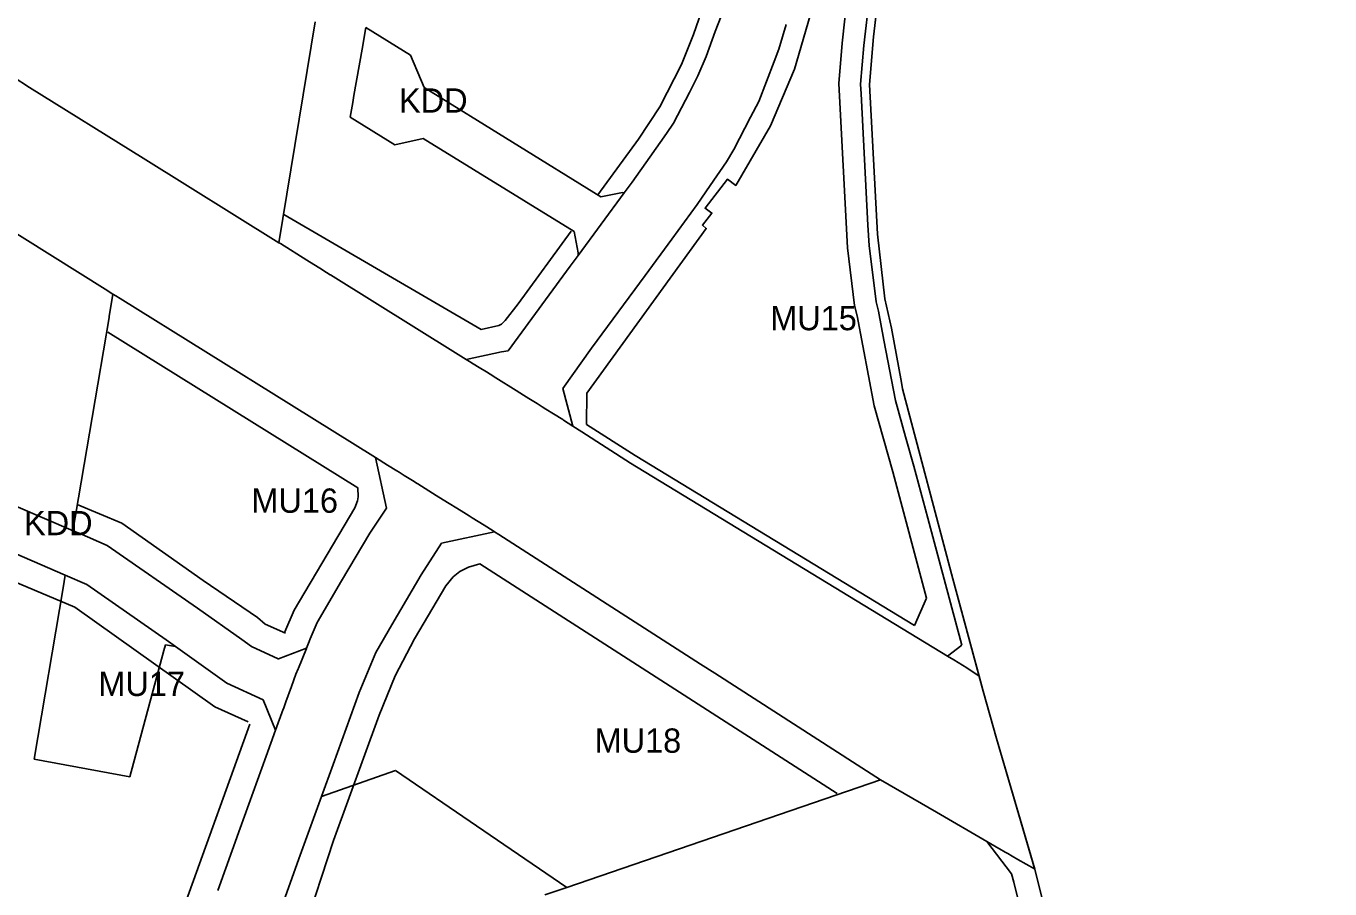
# Model space of a CAD drawing. Extents: x 7428080 to 7432143, y 5545880 to 5549217.
# Drawn here: x 7430887.1 to 7431185, y 5547031.3 to 5547228.4 of the extents above; entities that cross this region are included whole.
import ezdxf

# ---------------------------------------------------------------- set-up
doc = ezdxf.new("R2010")
doc.units = 0
for name, color, linetype in [('CZ_L_granica obszaru objętego planem', 7, 'Continuous'), ('CZ_L_linie rozgraniczające tereny o różnym przeznaczeniu oraz różnych warunkach ich zabudowy i zagospodarowania', 7, 'Continuous'), ('CZ_L_maksymalne nieprzekraczalne linie zabudowy', 7, 'Continuous'), ('CZ_L_opisy_linie rozgraniczające tereny o różnym przeznaczeniu oraz różnych warunkach ich zabudowy i zagospodarowania', 7, 'Continuous')]:
    doc.layers.add(name, color=color, linetype=linetype)

msp = doc.modelspace()

# ---------------------------------------------------------------- linework, layer by layer
at = {"layer": 'CZ_L_granica obszaru objętego planem'}
for p, q in [((7431083.35, 5547248.03), (7431080.69, 5547225.95)), ((7431080.69, 5547225.95), (7431079.79, 5547215.06)), ((7431079.79, 5547215.06), (7431081.67, 5547180.91)), ((7431081.67, 5547180.91), (7431083.32, 5547166.12)), ((7431083.32, 5547166.12), (7431084.84, 5547159.41)), ((7431084.84, 5547159.41), (7431087.12, 5547146.98)), ((7431087.12, 5547146.98), (7431087.38, 5547145.53)), ((7431087.38, 5547145.53), (7431098.88, 5547102.12)), ((7431098.88, 5547102.12), (7431105.77, 5547076.46)), ((7431105.77, 5547076.46), (7431108.82, 5547065.62)), ((7431108.82, 5547065.62), (7431117.61, 5547035.75)), ((7431117.61, 5547035.75), (7431121.32, 5547020.82))]:
    msp.add_line(p, q, dxfattribs=at)
at = {"layer": 'CZ_L_linie rozgraniczające tereny o różnym przeznaczeniu oraz różnych warunkach ich zabudowy i zagospodarowania'}
for p, q in [((7431080.54, 5547241.86), (7431078.52, 5547223.98)), ((7430944.87, 5547178.9), (7430953.17, 5547229.4)), ((7431045.9, 5547230.71), (7431044.58, 5547227.18)), ((7430964.71, 5547228.06), (7430963.85, 5547223.13)), ((7430974.92, 5547221.75), (7430964.71, 5547228.06)), ((7431044.58, 5547227.18), (7431042.46, 5547221.47)), ((7431059.1, 5547223.16), (7431060.78, 5547228.77)), ((7430963.85, 5547223.13), (7430961.99, 5547212.53)), ((7430963.85, 5547223.13), (7430963.85, 5547223.13)), ((7431058.01, 5547220.33), (7431059.1, 5547223.16)), ((7431078.52, 5547223.98), (7431077.77, 5547215.15)), ((7430887.88, 5547214.39), (7430874.73, 5547222.87)), ((7430978.01, 5547214.39), (7430974.92, 5547221.75)), ((7431042.46, 5547221.47), (7431040.61, 5547217.03)), ((7431054.49, 5547211.2), (7431058.01, 5547220.33)), ((7430913.85, 5547198.22), (7430887.88, 5547214.39)), ((7431018.42, 5547189.42), (7430978.01, 5547214.39)), ((7431040.61, 5547217.03), (7431038.71, 5547213.27)), ((7431077.77, 5547215.15), (7431077.87, 5547212.96)), ((7430961.99, 5547212.53), (7430961.71, 5547210.92)), ((7431038.71, 5547213.27), (7431035.02, 5547206.25)), ((7431052.64, 5547207.64), (7431054.49, 5547211.2)), ((7431077.87, 5547212.96), (7431079.41, 5547182.9)), ((7430961.71, 5547210.92), (7430961.13, 5547207.61)), ((7430961.13, 5547207.61), (7430971.33, 5547201.3)), ((7431035.02, 5547206.25), (7431033.39, 5547203.87)), ((7431048.79, 5547200.23), (7431052.64, 5547207.64)), ((7430971.33, 5547201.3), (7430977.83, 5547202.74)), ((7430977.83, 5547202.74), (7431012.3, 5547181.45)), ((7431033.39, 5547203.87), (7431029.6, 5547198.43)), ((7431047.14, 5547197.41), (7431048.79, 5547200.23)), ((7430944.87, 5547178.9), (7430913.85, 5547198.22)), ((7431029.6, 5547198.43), (7431025.55, 5547192.79)), ((7431043.42, 5547191.99), (7431047.14, 5547197.41)), ((7431023.75, 5547190.33), (7431013.26, 5547176.03)), ((7431023.34, 5547190.37), (7431018.42, 5547189.42)), ((7431023.75, 5547190.33), (7431023.34, 5547190.37)), ((7431025.55, 5547192.79), (7431023.75, 5547190.33)), ((7431040.41, 5547187.68), (7431043.42, 5547191.99)), ((7430871.92, 5547188.98), (7430905.11, 5547168.32)), ((7431034.61, 5547179.76), (7431040.41, 5547187.68)), ((7431012.3, 5547181.45), (7431013.23, 5547176.59)), ((7431079.41, 5547182.9), (7431079.74, 5547178.29)), ((7430945.18, 5547178.71), (7430944.87, 5547178.9)), ((7430951.25, 5547174.93), (7430945.18, 5547178.71)), ((7431028.52, 5547171.43), (7431034.61, 5547179.76)), ((7431013.26, 5547176.03), (7431011.44, 5547173.55)), ((7431013.23, 5547176.59), (7431013.26, 5547176.03)), ((7431079.74, 5547178.29), (7431081.32, 5547165.45)), ((7430954.81, 5547172.71), (7430951.25, 5547174.93)), ((7430954.87, 5547172.67), (7430954.81, 5547172.71)), ((7430956.6, 5547171.6), (7430954.87, 5547172.67)), ((7431011.44, 5547173.55), (7431005.77, 5547165.86)), ((7430956.62, 5547171.58), (7430956.6, 5547171.6)), ((7430956.63, 5547171.58), (7430956.62, 5547171.58)), ((7430985.8, 5547153.41), (7430956.63, 5547171.58)), ((7430956.63, 5547171.58), (7430956.63, 5547171.58)), ((7431016.28, 5547154.85), (7431028.52, 5547171.43)), ((7430905.11, 5547168.32), (7430906.9, 5547167.2)), ((7430906.9, 5547167.2), (7430906.09, 5547162.04)), ((7430906.9, 5547167.2), (7430907.6, 5547166.77)), ((7430907.6, 5547166.77), (7430908.58, 5547166.16)), ((7430908.58, 5547166.16), (7430947.72, 5547141.79)), ((7431005.77, 5547165.86), (7430997.25, 5547154.25)), ((7431081.32, 5547165.45), (7431081.9, 5547163.27)), ((7430906.05, 5547161.84), (7430903.45, 5547146.57)), ((7430906.09, 5547162.04), (7430906.05, 5547161.84)), ((7431081.9, 5547163.27), (7431083.06, 5547156.68)), ((7431009.73, 5547145.58), (7431016.28, 5547154.85)), ((7431083.06, 5547156.68), (7431085.77, 5547142.86)), ((7430987.64, 5547152.27), (7430985.8, 5547153.41)), ((7430995.68, 5547153.96), (7430987.64, 5547152.27)), ((7430987.64, 5547152.27), (7430988.41, 5547151.79)), ((7430988.41, 5547151.79), (7430988.6, 5547151.67)), ((7430988.6, 5547151.67), (7430990.26, 5547150.64)), ((7430997.25, 5547154.25), (7430995.68, 5547153.96)), ((7430990.26, 5547150.64), (7430992.64, 5547149.16)), ((7430992.64, 5547149.16), (7430992.78, 5547149.09)), ((7430992.78, 5547149.09), (7430993.12, 5547148.88)), ((7430993.12, 5547148.88), (7430994.41, 5547148.07)), ((7430903.45, 5547146.57), (7430899.03, 5547120.61)), ((7430994.41, 5547148.07), (7430999.08, 5547145.15)), ((7430999.08, 5547145.15), (7431000.72, 5547144.12)), ((7431000.72, 5547144.12), (7431000.76, 5547144.1)), ((7431000.76, 5547144.1), (7431002, 5547143.33)), ((7431002, 5547143.33), (7431003.83, 5547142.19)), ((7431012.04, 5547137.04), (7431009.73, 5547145.58)), ((7431085.77, 5547142.86), (7431088.03, 5547134.57)), ((7430947.72, 5547141.79), (7430966.9, 5547129.85)), ((7431003.83, 5547142.19), (7431005.01, 5547141.45)), ((7431005.01, 5547141.45), (7431005.85, 5547140.93)), ((7431005.85, 5547140.93), (7431007.63, 5547139.82)), ((7431007.63, 5547139.82), (7431009.75, 5547138.51)), ((7431009.75, 5547138.51), (7431009.84, 5547138.44)), ((7431009.84, 5547138.44), (7431009.92, 5547138.4)), ((7431009.92, 5547138.4), (7431012.04, 5547137.04)), ((7431014.07, 5547135.73), (7431012.04, 5547137.04)), ((7431025.19, 5547128.59), (7431014.07, 5547135.73)), ((7431088.03, 5547134.57), (7431089.98, 5547127.91)), ((7430969.69, 5547128.11), (7430966.9, 5547129.85)), ((7430966.9, 5547129.85), (7430969.4, 5547118.27)), ((7430971.79, 5547126.8), (7430969.69, 5547128.11)), ((7431097.67, 5547084.49), (7431025.19, 5547128.59)), ((7431089.98, 5547127.91), (7431093.13, 5547116.01)), ((7430972.32, 5547126.47), (7430971.79, 5547126.8)), ((7430973.45, 5547125.77), (7430972.32, 5547126.47)), ((7430975.35, 5547124.59), (7430973.45, 5547125.77)), ((7430976.42, 5547123.92), (7430975.35, 5547124.59)), ((7430976.62, 5547123.8), (7430976.42, 5547123.92)), ((7430980.81, 5547121.19), (7430976.62, 5547123.8)), ((7430897.8, 5547113.13), (7430884.23, 5547118.97)), ((7430899.03, 5547120.61), (7430898.27, 5547116.14)), ((7430983.39, 5547119.58), (7430980.81, 5547121.19)), ((7430984.55, 5547118.86), (7430983.39, 5547119.58)), ((7430984.75, 5547118.73), (7430984.55, 5547118.86)), ((7430898.27, 5547116.14), (7430898.13, 5547115.28)), ((7430969.4, 5547118.27), (7430965.64, 5547112.54)), ((7430985.54, 5547118.24), (7430984.75, 5547118.73)), ((7430987.09, 5547117.27), (7430985.54, 5547118.24)), ((7430988.35, 5547116.49), (7430987.09, 5547117.27)), ((7430988.75, 5547116.24), (7430988.35, 5547116.49)), ((7430988.99, 5547116.09), (7430988.75, 5547116.24)), ((7430991.74, 5547114.38), (7430988.99, 5547116.09)), ((7431093.13, 5547116.01), (7431100.88, 5547087)), ((7430898.13, 5547115.28), (7430897.8, 5547113.13)), ((7430899.16, 5547112.54), (7430897.8, 5547113.13)), ((7430982.04, 5547110.26), (7430994.14, 5547112.88)), ((7430993.8, 5547113.1), (7430991.74, 5547114.38)), ((7430994.14, 5547112.88), (7430993.8, 5547113.1)), ((7430994.14, 5547112.88), (7430995.11, 5547112.26)), ((7430899.17, 5547112.53), (7430899.16, 5547112.54)), ((7430905.63, 5547109.72), (7430899.17, 5547112.53)), ((7430965.64, 5547112.54), (7430959.18, 5547101.69)), ((7430977.34, 5547103.03), (7430982.04, 5547110.26)), ((7430995.11, 5547112.26), (7431041.18, 5547082.67)), ((7430880.83, 5547109.55), (7430896.03, 5547103)), ((7430926.27, 5547095.41), (7430905.63, 5547109.72)), ((7430896.03, 5547103), (7430895.55, 5547100.11)), ((7430896.03, 5547103), (7430900.99, 5547100.86)), ((7430959.18, 5547101.69), (7430953.61, 5547092.15)), ((7430970.65, 5547091.59), (7430977.34, 5547103.03)), ((7430895.55, 5547100.11), (7430888.91, 5547060.91)), ((7430900.99, 5547100.86), (7430919.09, 5547088.23)), ((7430936.34, 5547088.28), (7430926.27, 5547095.41)), ((7430926.27, 5547095.41), (7430926.27, 5547095.41)), ((7430953.61, 5547092.15), (7430952.03, 5547088.44)), ((7430966.98, 5547085.32), (7430970.65, 5547091.59)), ((7430918.58, 5547085.77), (7430918.91, 5547087.02)), ((7430918.91, 5547087.02), (7430921.23, 5547086.69)), ((7430919.09, 5547088.23), (7430921.23, 5547086.69)), ((7430921.23, 5547086.69), (7430932.92, 5547078.26)), ((7430938.58, 5547086.67), (7430936.34, 5547088.28)), ((7430944.7, 5547083.86), (7430938.58, 5547086.67)), ((7430951.17, 5547086.33), (7430944.75, 5547083.87)), ((7430949.3, 5547081.75), (7430951.13, 5547086.22)), ((7430951.13, 5547086.22), (7430951.17, 5547086.33)), ((7430951.77, 5547087.81), (7430951.17, 5547086.33)), ((7430952.03, 5547088.44), (7430951.77, 5547087.81)), ((7431100.88, 5547087), (7431097.67, 5547084.49)), ((7430910.79, 5547056.89), (7430918.58, 5547085.77)), ((7430944.75, 5547083.87), (7430944.7, 5547083.86)), ((7430963.18, 5547076.18), (7430966.98, 5547085.32)), ((7431099.1, 5547083.63), (7431097.67, 5547084.49)), ((7431100.05, 5547083.04), (7431099.1, 5547083.63)), ((7430947.7, 5547077.5), (7430948.73, 5547080.33)), ((7430948.73, 5547080.33), (7430949.23, 5547081.58)), ((7430949.23, 5547081.58), (7430949.3, 5547081.75)), ((7431041.18, 5547082.67), (7431044.48, 5547080.55)), ((7431044.48, 5547080.55), (7431077.03, 5547059.64)), ((7431102.08, 5547081.81), (7431100.05, 5547083.04)), ((7431104.84, 5547079.92), (7431102.08, 5547081.81)), ((7430932.92, 5547078.26), (7430941.25, 5547074.47)), ((7430946.46, 5547074.07), (7430947.7, 5547077.5)), ((7430941.25, 5547074.47), (7430944.1, 5547067.53)), ((7430957.24, 5547059.74), (7430963.18, 5547076.18)), ((7430944.1, 5547067.53), (7430945.86, 5547072.38)), ((7430945.86, 5547072.38), (7430945.87, 5547072.42)), ((7430945.87, 5547072.42), (7430946.46, 5547074.07)), ((7430944.1, 5547067.53), (7430941.96, 5547061.6)), ((7430888.91, 5547060.91), (7430910.79, 5547056.89)), ((7430941.96, 5547061.6), (7430936.02, 5547045.16)), ((7430954.6, 5547052.44), (7430957.24, 5547059.74)), ((7431077.03, 5547059.64), (7431082.31, 5547056.25)), ((7430971.46, 5547058.31), (7430954.6, 5547052.44)), ((7430989.99, 5547045.71), (7430971.46, 5547058.31)), ((7431010.64, 5547031.63), (7431082.31, 5547056.25)), ((7431082.31, 5547056.25), (7431095.1, 5547048.81)), ((7430954.6, 5547052.44), (7430949.44, 5547038.17)), ((7431095.1, 5547048.81), (7431106.62, 5547042.11)), ((7430936.02, 5547045.16), (7430930.9, 5547030.96)), ((7431010.64, 5547031.63), (7430989.99, 5547045.71)), ((7431106.62, 5547042.11), (7431112.23, 5547034.76)), ((7431106.62, 5547042.11), (7431109.4, 5547040.49)), ((7431109.4, 5547040.49), (7431109.54, 5547040.42)), ((7431109.54, 5547040.42), (7431110.78, 5547039.71)), ((7431110.78, 5547039.71), (7431111.39, 5547039.35)), ((7431111.39, 5547039.35), (7431112.44, 5547038.75)), ((7431112.44, 5547038.75), (7431113.74, 5547038.01)), ((7430949.44, 5547038.17), (7430944.73, 5547025.11)), ((7431113.74, 5547038.01), (7431117.48, 5547035.87)), ((7431117.48, 5547035.87), (7431117.6, 5547035.79)), ((7431112.23, 5547034.76), (7431112.76, 5547032.83)), ((7431112.76, 5547032.83), (7431116.28, 5547019.02)), ((7431005.65, 5547029.91), (7431010.64, 5547031.63))]:
    msp.add_line(p, q, dxfattribs=at)
for points in [[(7431068.35, 5547275.39), (7431069.54, 5547275.12), (7431084.96, 5547272.05), (7431085.82, 5547270.13), (7431083.35, 5547248.03), (7431080.69, 5547225.95), (7431079.79, 5547215.06), (7431081.67, 5547180.91), (7431083.32, 5547166.12), (7431084.84, 5547159.41), (7431087.12, 5547146.98), (7431087.38, 5547145.53), (7431098.88, 5547102.12), (7431104.84, 5547079.92)], [(7431104.84, 5547079.92), (7431105.77, 5547076.46), (7431108.82, 5547065.62), (7431117.6, 5547035.79)], [(7431117.6, 5547035.79), (7431117.61, 5547035.75), (7431121.32, 5547020.82), (7431125.01, 5547005.39), (7431127.96, 5546992.25), (7431130.5, 5546978.83), (7431132.44, 5546965.83), (7431135.86, 5546952.34), (7431141.66, 5546937.67), (7431146.32, 5546932.9), (7431151.59, 5546927.62), (7431166.27, 5546909.37), (7431171.08, 5546903.28), (7431176.28, 5546895.82), (7431179.09, 5546891.28), (7431180.72, 5546888.65), (7431183.18, 5546884.54), (7431187.05, 5546877.6)]]:
    msp.add_lwpolyline(points, dxfattribs=at)
at = {"layer": 'CZ_L_maksymalne nieprzekraczalne linie zabudowy'}
for points in [[(7431017.73, 5547189.85), (7431027.03, 5547202.56), (7431031.87, 5547209.94), (7431036.83, 5547219.63), (7431039.6, 5547226.5), (7431041.43, 5547231.76), (7431042.67, 5547236.07), (7431043.87, 5547241.19), (7431045.56, 5547250.24), (7431047.92, 5547270.34), (7431043.85, 5547273.01), (7431035.58, 5547275.9), (7431025.98, 5547278.42), (7431017.33, 5547280.38), (7431010.34, 5547281.76), (7431004.39, 5547282.73), (7430993.11, 5547284.13), (7430957.52, 5547287.64), (7430940.59, 5547289.59), (7430878.65, 5547305.59), (7430870.04, 5547307.64), (7430821.75, 5547315.01)], [(7431090.11, 5547091.46), (7431092.85, 5547097.69), (7431085.16, 5547126.57), (7431080.91, 5547141.69), (7431077.01, 5547162.19), (7431076.4, 5547164.6), (7431074.76, 5547177.76), (7431072.77, 5547215.28), (7431073.56, 5547224.54), (7431078.12, 5547266.21)], [(7430654.54, 5547240.29), (7430665.61, 5547225.73), (7430675.78, 5547211.67), (7430680.29, 5547205.95), (7430715.45, 5547163.65), (7430765.79, 5547100.82), (7430780.35, 5547083.28), (7430800.05, 5547059.92), (7430816.12, 5547041.16), (7430824.8, 5547031.35), (7430886.76, 5546964.98), (7430896.64, 5546952.97), (7430901.69, 5546945.24), (7430901.95, 5546945.2), (7430902.39, 5546945.93), (7430903.3, 5546948.81), (7430911.71, 5546982.58), (7430913.18, 5546988.55), (7430923.67, 5547028.55), (7430938.24, 5547068.96)], [(7431068.38, 5547238.22), (7431062.7, 5547218.6), (7431057.21, 5547205.61), (7431049.24, 5547192.02), (7431047.37, 5547193.45), (7431042.25, 5547186.78), (7431043.8, 5547185.69), (7431041.62, 5547182.94), (7431042.49, 5547182.18), (7431015.18, 5547144.58), (7431015.15, 5547137.42), (7431026.25, 5547130.29), (7431090.11, 5547091.46)], [(7430937.82, 5547069.44), (7430930.19, 5547072.87), (7430898.18, 5547095.68), (7430871.92, 5547106.73), (7430867.46, 5547110.07), (7430846.33, 5547123.74), (7430798.67, 5547153.17), (7430756.26, 5547179.01), (7430752.36, 5547177.58), (7430738, 5547186.63), (7430740.91, 5547202.6)], [(7430945.98, 5547185.35), (7430991.06, 5547159.12), (7430995.11, 5547159.99), (7430995.7, 5547160.32), (7430996.55, 5547161.13), (7430999.54, 5547164.97), (7431011.67, 5547181.53)], [(7430946.21, 5547090.05), (7430948.34, 5547095.01), (7430962.19, 5547118.35), (7430962.79, 5547119.94), (7430962.96, 5547120.86), (7430962.86, 5547122.94), (7430905.77, 5547158.49)], [(7430898.77, 5547119.08), (7430908.96, 5547114.84), (7430927.55, 5547101.72), (7430939.94, 5547093.27), (7430941.71, 5547091.76), (7430946.38, 5547089.72)], [(7431072.4, 5547053.11), (7430990.73, 5547105.56), (7430988.19, 5547104.82), (7430986.23, 5547103.84), (7430984.69, 5547102.6), (7430982.99, 5547100.5), (7430975.84, 5547088.45), (7430971.39, 5547079.97), (7430967.74, 5547071), (7430957.36, 5547042.33), (7430950.55, 5547021.67), (7430946.38, 5547007.73), (7430943.31, 5546996.83), (7430936.67, 5546971.18)]]:
    msp.add_lwpolyline(points, dxfattribs=at)

# ---------------------------------------------------------------- texts
at = {"layer": 'CZ_L_opisy_linie rozgraniczające tereny o różnym przeznaczeniu oraz różnych warunkach ich zabudowy i zagospodarowania'}
for s, p in [('KDD', (7430972.3, 5547208.64)), ('MU15', (7431057.12, 5547158.93)), ('MU16', (7430938.56, 5547117.23)), ('KDD', (7430886.61, 5547112.1)), ('MU17', (7430903.58, 5547075.36)), ('MU18', (7431016.99, 5547062.4))]:
    msp.add_text(s, height=5.549, dxfattribs=at).set_placement(p)

doc.saveas('drawing.dxf')
